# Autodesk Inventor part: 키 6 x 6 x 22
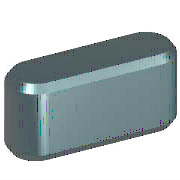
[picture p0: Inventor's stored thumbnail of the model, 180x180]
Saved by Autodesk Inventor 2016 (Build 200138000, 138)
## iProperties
IsCustomPart: 1
Created: 2012-02
Part Number: 키 6 x 6 x 22
Material: 강철, 연강
Description: 키 및 해당 키홈
Document SubType Name: Modeling
Standard: KS B 1311
Designer: mduedu
Standards Organization: KS
Language: ko-KR
Size Designation: 6 x 6 x 22
Categories: <MemberInstance><Categories><Category DisplayName="샤프트 부품" InternalName="7f7aeb1f-a693-4053-b835-cee3144e0d98" Mnemonic="SHFT"><Category DisplayName="키" Interna
Density: 7.86 g/cm^3
Mass: 5.79788 g
Surface Area: 5.294 cm^2
Volume: 0.737644 cm^3
Appearance: 노란색
Author: mduedu
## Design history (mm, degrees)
workplane "Work Plane1"
workplane "Work Plane2"
sketch "스케치1"
  geometry: L1 (3, 3)-(19, 3); L2 (19, -3)-(3, -3); L3 (0, 9.4)-(0, -7.4) reference; L4 (-5, 0)-(30, 0) reference; L5 (22, 0)-(22, 7); A1 r 3 centre (3, 0) between (3, 3) and (3, -3); A2 r 3 centre (19, 0) between (19, -3) and (19, 3)
  constraints: 6 end point, 5 point on circle, 4 tangent, 3 point on line, 2 centre point, 1 horizontal, 1 parallel, 1 perpendicular
  dimensions: "d0" = 3 radius of A1 (= 0.5 x PB); "d13" = 3 radius of A2 (= 0.5 x PB); "d14" = 22 distance between parallel lines of L5 L3 (= NLG)
extrude "본체1" new body sketch "스케치1" taper "d3" = 0 deg; stored distance "d4" = 10
workplane "Work Plane3"
body "Solid1"
chamfer "모따기1" distance "d8" = 0.4 (= PHH); stored, may be unused: second distance "d9" = 0.4 (= PHH), angle "d15" = 45 deg
other parameters: "d1" = -3.5 (= -PNT), "d2" = 2.5 (= PH - PNT), "NLG" = 22 [user parameter; used in 3 equation terms], "PB" = 6 [user parameter; used in 2 equation terms], "PNT" = 3.5 [user parameter; used in 2 equation terms], "PH" = 6 [user parameter; used in 1 equation term], "PHH" = 0.4 [user parameter; used in 2 equation terms], "d10" = 0, "d16" = 0, "d17" = 0, "d18" = 0, "WDMIN" = 17 [user parameter], "PLB2" = 22 (= NLG) [user parameter], "WDMAX" = 22 [user parameter], "PLB1" = 22 (= NLG) [user parameter], "RR" = 0.16 [user parameter], "PUEB" = 2.8 [user parameter]
